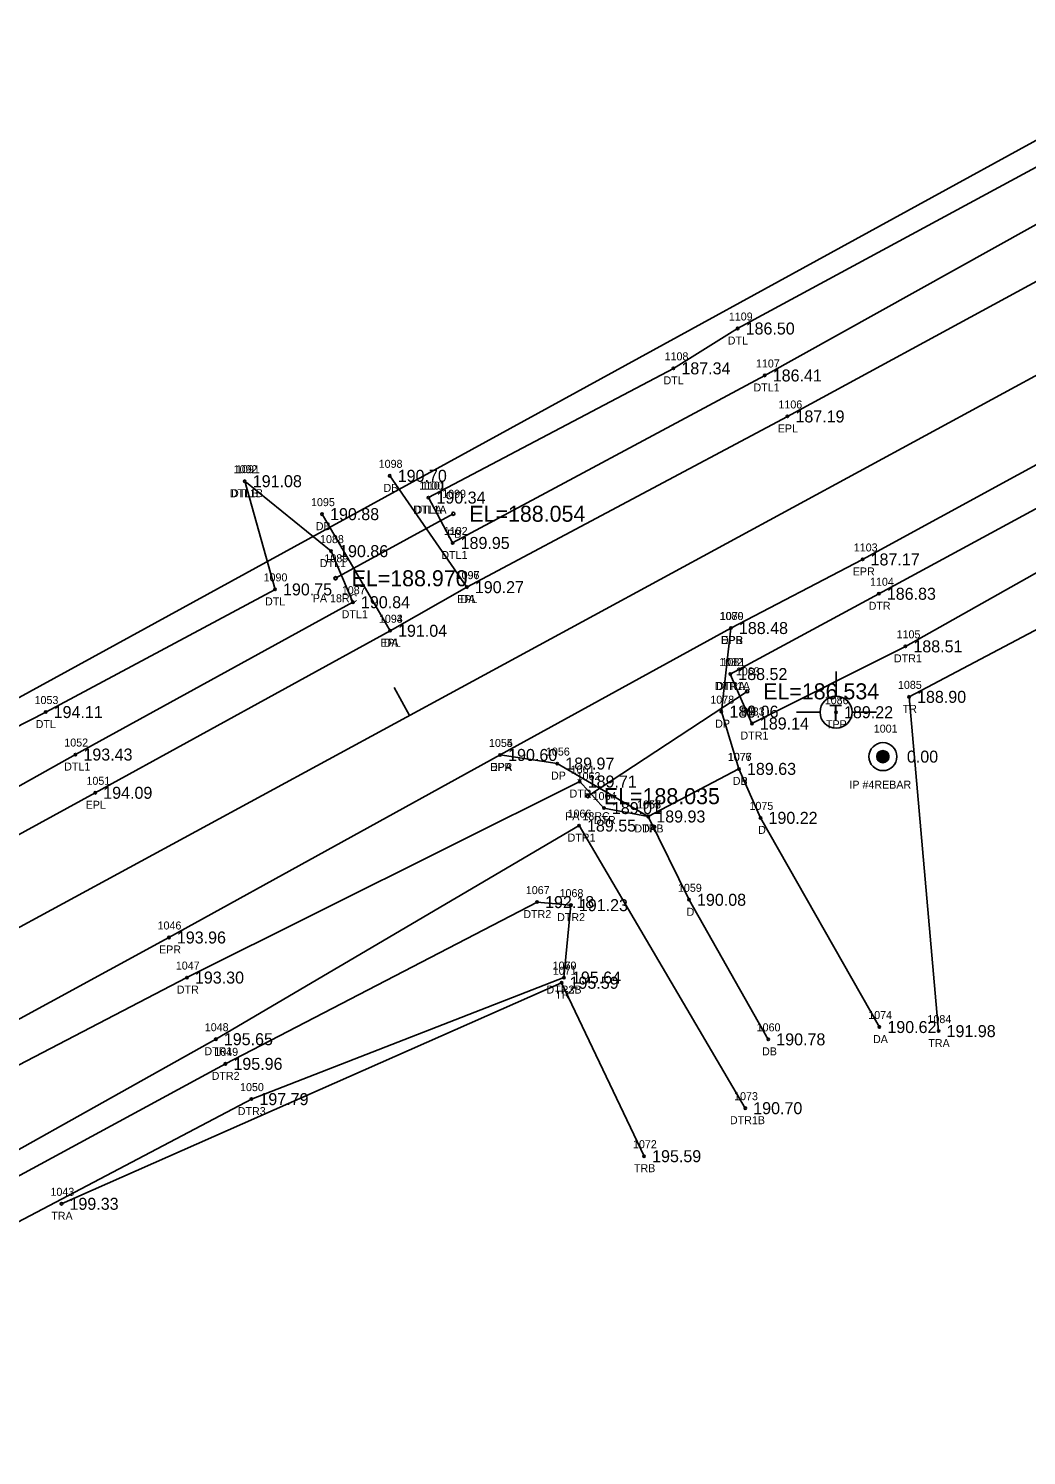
# Model space of a CAD drawing. Extents: x 2279339 to 2281902, y 1061267 to 1062892.
# Drawn here: x 2279628.3 to 2279753, y 1061403.7 to 1061582 of the extents above; entities that cross this region are included whole.
import ezdxf

# ---------------------------------------------------------------- set-up
doc = ezdxf.new("R2010")
doc.units = 0
for name, color, linetype in [('RD_EX_DR_Pipe', 7, 'Continuous'), ('RD_EX_DR_Pipe_txCode', 7, 'Continuous'), ('RD_EX_Driveway', 7, 'Continuous'), ('RD_EX_Driveway_txCode', 7, 'Continuous'), ('RD_EX_DV_Prop_txCode', 7, 'Continuous'), ('RD_EX_DV_PropPin', 7, 'Continuous'), ('RD_EX_H2O', 7, 'Continuous'), ('RD_EX_H2O_txCode', 7, 'Continuous'), ('RD_EX_Road', 7, 'Continuous'), ('RD_EX_Road_txCode', 7, 'Continuous'), ('RD_EX_TX_Driveway_ELEV', 7, 'Continuous'), ('RD_EX_TX_DV_Prop_ELEV', 7, 'Continuous'), ('RD_EX_TX_H2O_ELEV', 7, 'Continuous'), ('RD_EX_TX_Road_ELEV', 7, 'Continuous'), ('RD_EX_TX_UT_ELEV', 7, 'Continuous'), ('RD_EX_TX_VEG_ELEV', 7, 'Continuous'), ('RD_EX_UT', 7, 'Continuous'), ('RD_EX_UT_txCode', 7, 'Continuous'), ('RD_EX_VEG', 7, 'Continuous'), ('RD_EX_VEG_txCode', 7, 'Continuous'), ('RD_HC_Cl', 7, 'Continuous'), ('RD_HC_Data_Tic', 7, 'Continuous'), ('RD_SMD_Locator', 7, 'Continuous'), ('RD_TX_Pipe_ElevEX', 7, 'Continuous')]:
    doc.layers.add(name, color=color, linetype=linetype)

msp = doc.modelspace()

# ---------------------------------------------------------------- linework, layer by layer
at = {"layer": 'RD_EX_DR_Pipe'}
for p, q in [((2279666.65, 1061513.32), (2279681.37, 1061521.38)), ((2279698.19, 1061486.09), (2279718.1, 1061499.19))]:
    msp.add_line(p, q, dxfattribs=at)
at = {"layer": 'RD_EX_Driveway'}
for p, q in [((2279683.06, 1061512.21), (2279673.42, 1061526.12)), ((2279673.46, 1061506.76), (2279664.96, 1061521.33))]:
    msp.add_line(p, q, dxfattribs=at)
for points in [[(2279687.22, 1061491.24), (2279694.36, 1061490.16), (2279705.74, 1061483.55), (2279717.08, 1061489.5), (2279714.88, 1061496.65), (2279716.07, 1061507.1)], [(2279734.63, 1061457.24), (2279719.77, 1061483.38), (2279717.08, 1061489.5)], [(2279705.74, 1061483.55), (2279710.83, 1061473.14), (2279720.74, 1061455.7)]]:
    msp.add_lwpolyline(points, dxfattribs=at)
at = {"layer": 'RD_EX_DV_PropPin'}
for p, q in [((2279734.34, 1061490.83), (2279734.34, 1061491.23)), ((2279734.37, 1061490.73), (2279734.37, 1061491.33)), ((2279734.41, 1061490.66), (2279734.41, 1061491.4)), ((2279734.44, 1061490.6), (2279734.44, 1061491.46)), ((2279734.48, 1061490.55), (2279734.48, 1061491.5)), ((2279734.51, 1061490.51), (2279734.51, 1061491.54)), ((2279734.55, 1061490.48), (2279734.55, 1061491.58)), ((2279734.58, 1061490.45), (2279734.58, 1061491.61)), ((2279734.62, 1061490.42), (2279734.62, 1061491.64)), ((2279734.65, 1061490.39), (2279734.65, 1061491.66)), ((2279734.69, 1061490.37), (2279734.69, 1061491.69)), ((2279734.72, 1061490.35), (2279734.72, 1061491.7)), ((2279734.76, 1061490.34), (2279734.76, 1061491.72)), ((2279734.79, 1061490.32), (2279734.79, 1061491.74)), ((2279734.83, 1061490.31), (2279734.83, 1061491.75)), ((2279734.86, 1061490.3), (2279734.86, 1061491.76)), ((2279734.9, 1061490.29), (2279734.9, 1061491.77)), ((2279734.93, 1061490.28), (2279734.93, 1061491.78)), ((2279734.97, 1061490.28), (2279734.97, 1061491.78)), ((2279735, 1061490.27), (2279735, 1061491.79)), ((2279735.04, 1061490.27), (2279735.04, 1061491.79)), ((2279735.07, 1061490.27), (2279735.07, 1061491.79)), ((2279735.11, 1061490.27), (2279735.11, 1061491.79)), ((2279735.14, 1061490.27), (2279735.14, 1061491.79)), ((2279735.18, 1061490.28), (2279735.18, 1061491.78)), ((2279735.21, 1061490.28), (2279735.21, 1061491.78)), ((2279735.25, 1061490.29), (2279735.25, 1061491.77)), ((2279735.28, 1061490.3), (2279735.28, 1061491.76)), ((2279735.32, 1061490.31), (2279735.32, 1061491.75)), ((2279735.35, 1061490.32), (2279735.35, 1061491.74)), ((2279735.39, 1061490.34), (2279735.39, 1061491.72)), ((2279735.42, 1061490.35), (2279735.42, 1061491.7)), ((2279735.46, 1061490.37), (2279735.46, 1061491.69)), ((2279735.49, 1061490.39), (2279735.49, 1061491.66)), ((2279735.53, 1061490.42), (2279735.53, 1061491.64)), ((2279735.56, 1061490.45), (2279735.56, 1061491.61)), ((2279735.6, 1061490.48), (2279735.6, 1061491.58)), ((2279735.63, 1061490.51), (2279735.63, 1061491.54)), ((2279735.67, 1061490.55), (2279735.67, 1061491.5)), ((2279735.7, 1061490.6), (2279735.7, 1061491.46)), ((2279735.74, 1061490.66), (2279735.74, 1061491.4)), ((2279735.77, 1061490.73), (2279735.77, 1061491.33)), ((2279735.81, 1061490.83), (2279735.81, 1061491.23))]:
    msp.add_line(p, q, dxfattribs=at)
for radius in [1.75, 0.761]:
    msp.add_circle((2279735.07, 1061491.03), radius, dxfattribs=at)
at = {"layer": 'RD_EX_H2O'}
for points in [[(2279678.26, 1061523.4), (2279708.88, 1061539.55), (2279716.91, 1061544.53), (2279803.91, 1061591.58), (2279817.92, 1061601.16), (2279890.29, 1061645.53), (2279903.5, 1061647.72), (2279912.54, 1061647.23), (2279918.28, 1061645.97)], [(2279678.26, 1061523.4), (2279681.28, 1061517.73), (2279720.3, 1061538.66), (2279806.21, 1061586.46), (2279822.44, 1061595.21), (2279894.25, 1061633.83), (2279918.28, 1061645.97)], [(2279715.99, 1061501.35), (2279734.56, 1061511.38), (2279821.65, 1061558.53), (2279857.43, 1061578.68), (2279860, 1061573.39)], [(2279715.99, 1061501.35), (2279718.69, 1061495.17), (2279737.88, 1061504.81), (2279824.53, 1061553.58), (2279860, 1061573.39)], [(2279546.29, 1061453.71), (2279630.41, 1061496.6), (2279659.08, 1061511.93), (2279655.3, 1061525.45)], [(2279552, 1061445.3), (2279634.13, 1061491.29), (2279668.82, 1061510.33), (2279666.09, 1061516.71), (2279655.3, 1061525.45)], [(2279564.82, 1061420.11), (2279648.07, 1061463.42), (2279697.17, 1061487.92), (2279700.19, 1061484.6), (2279705.74, 1061483.55)], [(2279569.22, 1061409.58), (2279651.68, 1061455.72), (2279697.08, 1061482.41), (2279717.86, 1061447.1)], [(2279569.64, 1061407.53), (2279652.88, 1061452.64), (2279691.84, 1061472.85), (2279696.06, 1061472.47), (2279695.2, 1061463.42)], [(2279571.45, 1061403.7), (2279656.13, 1061448.23), (2279695.2, 1061463.42)]]:
    msp.add_lwpolyline(points, dxfattribs=at)
at = {"layer": 'RD_EX_Road'}
for points in [[(2279554.31, 1061441.46), (2279636.61, 1061486.51), (2279673.46, 1061506.76), (2279683.06, 1061512.21), (2279723.14, 1061533.54), (2279809.28, 1061580.29), (2279896.91, 1061627.91), (2279977.07, 1061671.02), (2280059.64, 1061715.57), (2280142.91, 1061760.72), (2280228.83, 1061807.06), (2280306.04, 1061849.18), (2280392.98, 1061896.71), (2280482.82, 1061945.75), (2280567.83, 1061991.78), (2280649.94, 1062036.55), (2280660.56, 1062042.19), (2280676.12, 1062050.66), (2280737.28, 1062083.64), (2280828.54, 1062132.77), (2280887.86, 1062164.61), (2280934.91, 1062190.9)], [(2279563.73, 1061423.75), (2279645.81, 1061468.43), (2279687.22, 1061491.24), (2279716.07, 1061507.1), (2279732.53, 1061515.67), (2279819.45, 1061563.03), (2279856.79, 1061583.22), (2279872.52, 1061591.57), (2279906, 1061609.76), (2279987.33, 1061653.65)]]:
    msp.add_lwpolyline(points, dxfattribs=at)
at = {"layer": 'RD_EX_UT'}
for p, q in [((2279729.21, 1061501.65), (2279729.21, 1061498.58)), ((2279724.28, 1061496.6), (2279727.21, 1061496.6)), ((2279731.21, 1061496.6), (2279734.28, 1061496.6))]:
    msp.add_line(p, q, dxfattribs=at)
msp.add_circle((2279729.21, 1061496.58), 2, dxfattribs=at)
at = {"layer": 'RD_EX_VEG'}
for points in [[(2279558.89, 1061483.89), (2279567.79, 1061465.98), (2279895.37, 1061645.37), (2280383.77, 1061911.19), (2280927.05, 1062203.11)], [(2279742.03, 1061456.73), (2279738.34, 1061498.5), (2279914.03, 1061591.25), (2280293.74, 1061794.82), (2280950.97, 1062158.54)], [(2279632.39, 1061435.15), (2279694.9, 1061462.77), (2279705.22, 1061441.1)]]:
    msp.add_lwpolyline(points, dxfattribs=at)
at = {"layer": 'RD_HC_Cl'}
msp.add_line((2279559.77, 1061433.17), (2280939.55, 1062181.67), dxfattribs=at)
at = {"layer": 'RD_HC_Data_Tic'}
msp.add_line((2279675.88, 1061496.16), (2279673.97, 1061499.67), dxfattribs=at)
at = {"layer": 'RD_SMD_Locator'}
for centre, radius in [((2279716.91, 1061544.53), 0.15), ((2279708.88, 1061539.55), 0.15), ((2279720.3, 1061538.66), 0.15), ((2279723.14, 1061533.54), 0.15), ((2279673.42, 1061526.12), 0.15), ((2279655.3, 1061525.45), 0.15), ((2279655.3, 1061525.45), 0.15), ((2279678.26, 1061523.4), 0.15), ((2279678.26, 1061523.4), 0.15), ((2279664.96, 1061521.33), 0.15), ((2279681.37, 1061521.38), 0.2), ((2279681.28, 1061517.73), 0.15), ((2279666.09, 1061516.71), 0.15), ((2279732.53, 1061515.67), 0.15), ((2279659.08, 1061511.93), 0.15), ((2279666.65, 1061513.32), 0.2), ((2279683.06, 1061512.21), 0.15), ((2279683.06, 1061512.21), 0.15), ((2279668.82, 1061510.33), 0.15), ((2279734.56, 1061511.38), 0.15), ((2279673.46, 1061506.76), 0.15), ((2279673.46, 1061506.76), 0.15), ((2279716.07, 1061507.1), 0.15), ((2279716.07, 1061507.1), 0.15), ((2279737.88, 1061504.81), 0.15), ((2279715.99, 1061501.35), 0.15), ((2279715.99, 1061501.35), 0.15), ((2279718.1, 1061499.19), 0.2), ((2279738.34, 1061498.5), 0.15), ((2279630.41, 1061496.6), 0.15), ((2279714.88, 1061496.65), 0.15), ((2279729.21, 1061496.58), 0.15), ((2279718.69, 1061495.17), 0.15), ((2279634.13, 1061491.29), 0.15), ((2279687.22, 1061491.24), 0.15), ((2279687.22, 1061491.24), 0.15), ((2279735.07, 1061491.03), 0.15), ((2279694.36, 1061490.16), 0.15), ((2279717.08, 1061489.5), 0.15), ((2279717.08, 1061489.5), 0.15), ((2279697.17, 1061487.92), 0.15), ((2279636.61, 1061486.51), 0.15), ((2279698.19, 1061486.09), 0.2), ((2279700.19, 1061484.6), 0.15), ((2279705.74, 1061483.55), 0.15), ((2279705.74, 1061483.55), 0.15), ((2279705.74, 1061483.55), 0.15), ((2279719.77, 1061483.38), 0.15), ((2279697.08, 1061482.41), 0.15), ((2279691.84, 1061472.85), 0.15), ((2279710.83, 1061473.14), 0.15), ((2279696.06, 1061472.47), 0.15), ((2279645.81, 1061468.43), 0.15), ((2279648.07, 1061463.42), 0.15), ((2279694.9, 1061462.77), 0.15), ((2279695.2, 1061463.42), 0.15), ((2279695.2, 1061463.42), 0.15), ((2279734.63, 1061457.24), 0.15), ((2279742.03, 1061456.73), 0.15), ((2279651.68, 1061455.72), 0.15), ((2279720.74, 1061455.7), 0.15), ((2279652.88, 1061452.64), 0.15), ((2279656.13, 1061448.23), 0.15), ((2279717.86, 1061447.1), 0.15), ((2279705.22, 1061441.1), 0.15), ((2279632.39, 1061435.15), 0.15)]:
    msp.add_circle(centre, radius, dxfattribs=at)

# ---------------------------------------------------------------- texts
at = {"layer": 'RD_EX_DR_Pipe_txCode'}
for s, p in [('1099', (2279679.98, 1061523.38)), ('PB', (2279680.59, 1061518.38)), ('1089', (2279665.26, 1061515.32)), ('PA 18RC', (2279663.8, 1061510.32)), ('1063', (2279716.69, 1061501.19)), ('PB', (2279717.32, 1061496.19)), ('1062', (2279696.78, 1061488.09)), ('PA 18RC', (2279695.35, 1061483.09))]:
    msp.add_text(s, height=1, dxfattribs=at).set_placement(p)
at = {"layer": 'RD_EX_Driveway_txCode'}
for s, p in [('1098', (2279672.04, 1061527.12)), ('DB', (2279672.64, 1061524.12)), ('1095', (2279663.58, 1061522.33)), ('DB', (2279664.18, 1061519.33)), ('1096', (2279681.65, 1061513.21)), ('DA', (2279682.27, 1061510.21)), ('1094', (2279672.07, 1061507.76)), ('1079', (2279714.69, 1061508.1)), ('DA', (2279672.66, 1061504.76)), ('DPB', (2279714.82, 1061505.1)), ('1078', (2279713.5, 1061497.65)), ('DP', (2279714.1, 1061494.65)), ('1055', (2279685.83, 1061492.24)), ('1056', (2279692.95, 1061491.16)), ('1076', (2279715.67, 1061490.5)), ('1077', (2279715.7, 1061490.5)), ('DPA', (2279685.95, 1061489.24)), ('DP', (2279693.58, 1061488.16)), ('DB', (2279716.3, 1061487.5)), ('DP', (2279716.3, 1061487.5)), ('1057', (2279704.36, 1061484.55)), ('1058', (2279704.36, 1061484.55)), ('1075', (2279718.39, 1061484.38)), ('DA', (2279704.95, 1061481.55)), ('DP', (2279704.96, 1061481.55)), ('D', (2279719.47, 1061481.38)), ('1059', (2279709.45, 1061474.14)), ('D', (2279710.53, 1061471.14)), ('1074', (2279733.24, 1061458.24)), ('1060', (2279719.29, 1061456.7)), ('DA', (2279733.83, 1061455.24)), ('DB', (2279719.96, 1061453.7))]:
    msp.add_text(s, height=1, dxfattribs=at).set_placement(p)
at = {"layer": 'RD_EX_DV_Prop_txCode'}
for s, p in [('1001', (2279733.93, 1061494.03)), ('IP #4REBAR', (2279730.88, 1061487.03))]:
    msp.add_text(s, height=1, dxfattribs=at).set_placement(p)
at = {"layer": 'RD_EX_H2O_txCode'}
for s, p in [('1109', (2279715.81, 1061545.53)), ('DTL', (2279715.67, 1061542.53)), ('1108', (2279707.78, 1061540.55)), ('1107', (2279719.2, 1061539.66)), ('DTL', (2279707.64, 1061537.55)), ('DTL1', (2279718.89, 1061536.66)), ('1092', (2279653.91, 1061526.45)), ('1091', (2279654.2, 1061526.45)), ('DTL1B', (2279653.42, 1061523.45)), ('DTLB', (2279653.58, 1061523.45)), ('1100', (2279677.12, 1061524.4)), ('1101', (2279677.44, 1061524.4)), ('DTL1A', (2279676.36, 1061521.4)), ('DTLA', (2279676.53, 1061521.4)), ('1102', (2279680.18, 1061518.73)), ('1088', (2279664.71, 1061517.71)), ('DTL1', (2279664.68, 1061514.71)), ('DTL1', (2279679.87, 1061515.73)), ('1090', (2279657.65, 1061512.93)), ('1087', (2279667.43, 1061511.33)), ('1104', (2279733.46, 1061512.38)), ('DTL', (2279657.83, 1061509.93)), ('DTR', (2279733.29, 1061509.38)), ('DTL1', (2279667.41, 1061508.33)), ('1105', (2279736.78, 1061505.81)), ('1082', (2279714.6, 1061502.35)), ('1081', (2279714.89, 1061502.35)), ('DTR1', (2279736.45, 1061502.81)), ('DTR1A', (2279714.07, 1061499.35)), ('DTRA', (2279714.23, 1061499.35)), ('1053', (2279629.02, 1061497.6)), ('1083', (2279717.31, 1061496.17)), ('DTL', (2279629.16, 1061494.6)), ('DTR1', (2279717.26, 1061493.17)), ('1052', (2279632.74, 1061492.29)), ('DTL1', (2279632.72, 1061489.29)), ('1061', (2279696.04, 1061488.92)), ('DTR', (2279695.9, 1061485.92)), ('1064', (2279698.78, 1061485.6)), ('1065', (2279704.33, 1061484.55)), ('1066', (2279695.65, 1061483.41)), ('DTR', (2279698.92, 1061482.6)), ('DTRB', (2279704, 1061481.55)), ('DTR1', (2279695.65, 1061480.41)), ('1067', (2279690.43, 1061473.85)), ('1068', (2279694.65, 1061473.47)), ('DTR2', (2279690.12, 1061470.85)), ('DTR2', (2279694.34, 1061470.47)), ('1047', (2279646.68, 1061464.42)), ('1070', (2279693.78, 1061464.42)), ('1069', (2279693.79, 1061464.42)), ('DTR', (2279646.8, 1061461.42)), ('DTR2B', (2279693.01, 1061461.42)), ('DTR3B', (2279693.01, 1061461.42)), ('1048', (2279650.3, 1061456.72)), ('DTR1', (2279650.25, 1061453.72)), ('1049', (2279651.49, 1061453.64)), ('DTR2', (2279651.16, 1061450.64)), ('1050', (2279654.71, 1061449.23)), ('1073', (2279716.47, 1061448.1)), ('DTR3', (2279654.42, 1061446.23)), ('DTR1B', (2279715.95, 1061445.1))]:
    msp.add_text(s, height=1, dxfattribs=at).set_placement(p)
at = {"layer": 'RD_EX_Road_txCode'}
for s, p in [('1106', (2279722.01, 1061534.54)), ('EPL', (2279721.93, 1061531.54)), ('1103', (2279731.43, 1061516.67)), ('1097', (2279681.67, 1061513.21)), ('EPR', (2279731.3, 1061513.67)), ('EPL', (2279681.86, 1061510.21)), ('1093', (2279672.07, 1061507.76)), ('1080', (2279714.65, 1061508.1)), ('EPL', (2279672.25, 1061504.76)), ('EPR', (2279714.84, 1061505.1)), ('1054', (2279685.83, 1061492.24)), ('EPR', (2279685.99, 1061489.24)), ('1051', (2279635.51, 1061487.51)), ('EPL', (2279635.41, 1061484.51)), ('1046', (2279644.4, 1061469.43)), ('EPR', (2279644.58, 1061466.43))]:
    msp.add_text(s, height=1, dxfattribs=at).set_placement(p)
at = {"layer": 'RD_EX_TX_Driveway_ELEV'}
for s, p in [('190.70', (2279674.42, 1061525.37)), ('190.88', (2279665.96, 1061520.58)), ('190.27', (2279684.06, 1061511.46)), ('191.04', (2279674.46, 1061506.01)), ('188.48', (2279717.07, 1061506.35)), ('189.06', (2279715.88, 1061495.9)), ('190.60', (2279688.22, 1061490.49)), ('189.97', (2279695.36, 1061489.41)), ('189.63', (2279718.08, 1061488.75)), ('189.63', (2279718.08, 1061488.75)), ('189.93', (2279706.74, 1061482.8)), ('189.93', (2279706.74, 1061482.8)), ('190.22', (2279720.77, 1061482.63)), ('190.08', (2279711.83, 1061472.39)), ('190.62', (2279735.63, 1061456.49)), ('190.78', (2279721.74, 1061454.95))]:
    msp.add_text(s, height=1.5, dxfattribs=at).set_placement(p)
at = {"layer": 'RD_EX_TX_DV_Prop_ELEV'}
msp.add_text('0.00', height=1.5, dxfattribs=at).set_placement((2279738.07, 1061490.28))
at = {"layer": 'RD_EX_TX_H2O_ELEV'}
for s, p in [('186.50', (2279717.91, 1061543.78)), ('187.34', (2279709.88, 1061538.8)), ('186.41', (2279721.3, 1061537.91)), ('191.08', (2279656.3, 1061524.7)), ('191.08', (2279656.3, 1061524.7)), ('190.34', (2279679.26, 1061522.65)), ('190.34', (2279679.26, 1061522.65)), ('190.86', (2279667.09, 1061515.96)), ('189.95', (2279682.28, 1061516.98)), ('190.75', (2279660.08, 1061511.18)), ('186.83', (2279735.56, 1061510.63)), ('190.84', (2279669.82, 1061509.58)), ('188.51', (2279738.88, 1061504.06)), ('188.52', (2279716.99, 1061500.6)), ('188.52', (2279716.99, 1061500.6)), ('194.11', (2279631.41, 1061495.85)), ('189.14', (2279719.69, 1061494.42)), ('193.43', (2279635.13, 1061490.54)), ('189.71', (2279698.17, 1061487.17)), ('189.01', (2279701.19, 1061483.85)), ('189.93', (2279706.74, 1061482.8)), ('189.55', (2279698.08, 1061481.66)), ('192.18', (2279692.84, 1061472.1)), ('191.23', (2279697.06, 1061471.72)), ('193.30', (2279649.07, 1061462.67)), ('195.64', (2279696.2, 1061462.67)), ('195.64', (2279696.2, 1061462.67)), ('195.65', (2279652.68, 1061454.97)), ('195.96', (2279653.88, 1061451.89)), ('197.79', (2279657.13, 1061447.48)), ('190.70', (2279718.86, 1061446.35))]:
    msp.add_text(s, height=1.5, dxfattribs=at).set_placement(p)
at = {"layer": 'RD_EX_TX_Road_ELEV'}
for s, p in [('187.19', (2279724.14, 1061532.79)), ('187.17', (2279733.53, 1061514.92)), ('190.27', (2279684.06, 1061511.46)), ('191.04', (2279674.46, 1061506.01)), ('188.48', (2279717.07, 1061506.35)), ('190.60', (2279688.22, 1061490.49)), ('194.09', (2279637.61, 1061485.76)), ('193.96', (2279646.81, 1061467.68))]:
    msp.add_text(s, height=1.5, dxfattribs=at).set_placement(p)
at = {"layer": 'RD_EX_TX_UT_ELEV'}
msp.add_text('189.22', height=1.5, dxfattribs=at).set_placement((2279730.21, 1061495.83))
at = {"layer": 'RD_EX_TX_VEG_ELEV'}
for s, p in [('188.90', (2279739.34, 1061497.75)), ('195.59', (2279695.9, 1061462.02)), ('191.98', (2279743.03, 1061455.98)), ('195.59', (2279706.22, 1061440.35)), ('199.33', (2279633.39, 1061434.4))]:
    msp.add_text(s, height=1.5, dxfattribs=at).set_placement(p)
at = {"layer": 'RD_EX_UT'}
msp.add_text('T', height=2, dxfattribs=at).set_placement((2279728.36, 1061495.54))
at = {"layer": 'RD_EX_UT_txCode'}
for s, p in [('1086', (2279727.8, 1061497.58)), ('TPP', (2279727.95, 1061494.58))]:
    msp.add_text(s, height=1, dxfattribs=at).set_placement(p)
at = {"layer": 'RD_EX_VEG_txCode'}
for s, p in [('1085', (2279736.95, 1061499.5)), ('TR', (2279737.54, 1061496.5)), ('1071', (2279693.8, 1061463.77)), ('TR', (2279694.11, 1061460.77)), ('1084', (2279740.64, 1061457.73)), ('TRA', (2279740.75, 1061454.73)), ('1072', (2279703.83, 1061442.1)), ('TRB', (2279703.95, 1061439.1)), ('1043', (2279631.01, 1061436.15)), ('TRA', (2279631.11, 1061433.15))]:
    msp.add_text(s, height=1, dxfattribs=at).set_placement(p)
at = {"layer": 'RD_TX_Pipe_ElevEX'}
for s, p in [('EL=188.054', (2279683.37, 1061520.38)), ('EL=188.970', (2279668.65, 1061512.32)), ('EL=186.534', (2279720.1, 1061498.19)), ('EL=188.035', (2279700.19, 1061485.09))]:
    msp.add_text(s, height=2, dxfattribs=at).set_placement(p)

doc.saveas('drawing.dxf')
